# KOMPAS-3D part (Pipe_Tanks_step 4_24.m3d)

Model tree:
1. X Axis
2. Y Axis
3. Z Axis  (labels: Bend 90 Dn 20; Pipe Dn 20)
     Òîëùèíà ñòåíêè 1 = 1

Referenced files in C:\Documents and Settings\kashirsky\Мои документы\Camtasia Studio\Pipelines3D\Tanks\: Tanks_step 4.a3d
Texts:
  Pipe Dn 20
  Steel ASTM A295
  Three Point Plane
  Plane at Angle
  Line and Point Plane
  Axis through Two Vertices
  Axis of Feature
  Axis of Conical Surface
  Axis through Edge
  Trim by Surface
  Trim by Sketch
  Feature with No History
  Intersection Axis of Two Planes
  Two Line Plane
  Line and Face Plane
  Bend by line
  Hole in sheet body
  Cut in sheet body
  Point in CM
  Linear Dimension from Line to Point
  Surface Finish Symbol
  Geometric Tolerance Symbol
  Leader #1
  Leader #2
  Leader #3
  Shape Deviations and Datum
  Node point number
  Mark of coordination axis
  Node point designation
  Mark/Reference designation with leader
  Mark/reference designation on line
  Mark/Reference designation without leader
  Bend 90 Dn 20
  Plane of section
